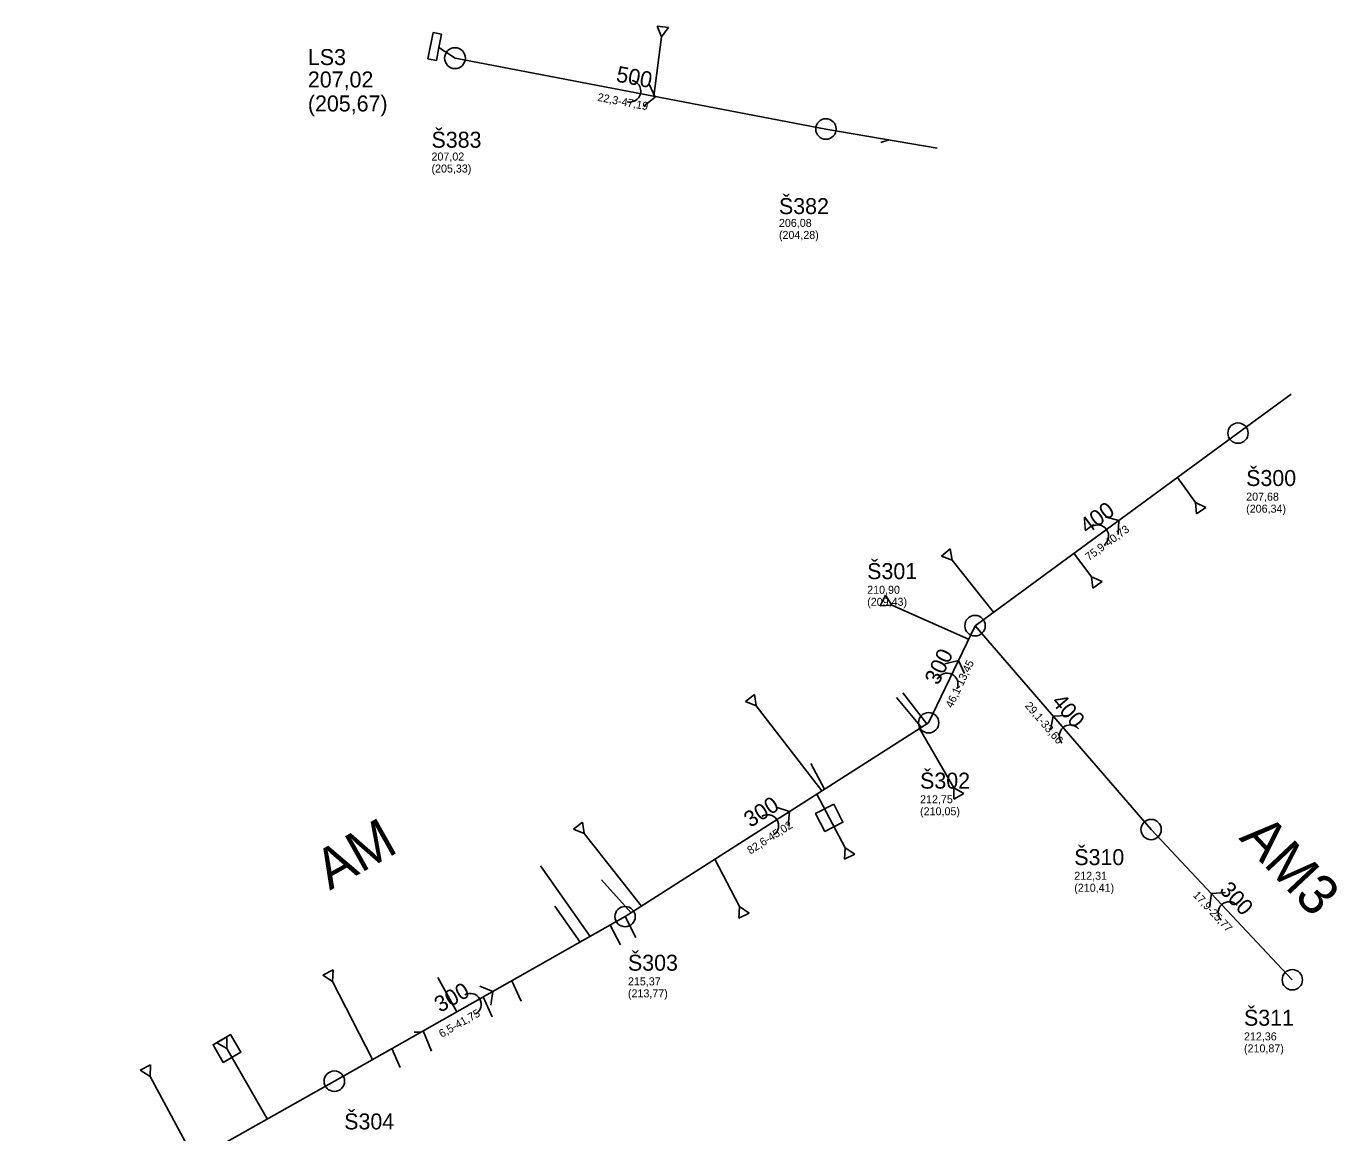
# Model space of a CAD drawing. Extents: x -574467 to -573663, y -1191209 to -1190406.
# Drawn here: x -574127.5 to -573963.7, y -1190544.6 to -1190406.2 of the extents above; entities that cross this region are included whole.
import ezdxf

# ---------------------------------------------------------------- set-up
doc = ezdxf.new("R2010")
doc.units = 0
for name, color, linetype in [('Vrstva 1', 7, 'Continuous'), ('Vrstva 12', 7, 'Continuous'), ('Vrstva 15', 7, 'Continuous'), ('Vrstva 29', 7, 'Continuous'), ('Vrstva 32', 7, 'Continuous'), ('Vrstva 35', 7, 'Continuous'), ('Vrstva 41', 7, 'Continuous'), ('Vrstva 44', 7, 'Continuous'), ('Vrstva 45', 7, 'Continuous'), ('Vrstva 56', 7, 'Continuous'), ('Vrstva 57', 7, 'Continuous')]:
    doc.layers.add(name, color=color, linetype=linetype)

# ---------------------------------------------------------------- blocks, each defined once
blk = doc.blocks.new('100')
at = {"layer": 'Vrstva 1'}
blk.add_circle((0, 0), 1.27, dxfattribs=at)
blk = doc.blocks.new('105')
at = {"layer": 'Vrstva 1'}
blk.add_lwpolyline([(-1.27, 1.27), (1.27, 1.27), (1.27, -1.27), (-1.27, -1.27), (-1.27, 1.27)], dxfattribs=at)
blk = doc.blocks.new('106')
at = {"layer": 'Vrstva 1'}
for p, q in [((1.25, 0.72), (0, 0)), ((0, 0), (1.25, -0.72)), ((1.25, -0.72), (1.25, 0.72))]:
    blk.add_line(p, q, dxfattribs=at)
blk = doc.blocks.new('91')
at = {"layer": 'Vrstva 1'}
blk.add_lwpolyline([(0.79, 1.37), (1.89, 0), (0.79, -1.38)], dxfattribs=at)
blk.add_arc((-1.37, 0), 1.37, 270, 90, dxfattribs=at)
blk = doc.blocks.new('86')
at = {"layer": 'Vrstva 1'}
blk.add_lwpolyline([(0.79, 1.37), (1.89, 0), (0.79, -1.38)], dxfattribs=at)
blk.add_arc((-1.37, 0), 1.37, 270, 90, dxfattribs=at)

msp = doc.modelspace()

# ---------------------------------------------------------------- linework, layer by layer
at = {"layer": 'Vrstva 12'}
for p, q in [((-574049.081, -1190414.968), (-574048.116, -1190407.558)), ((-574019.678, -1190420.432), (-574020.72, -1190420.75)), ((-573983.634, -1190462.641), (-573981.399, -1190465.764)), ((-573996.572, -1190472.118), (-573994.361, -1190475.053)), ((-574006.623, -1190479.48), (-574011.797, -1190472.997)), ((-574009.741, -1190482.866), (-574019.312, -1190478.584)), ((-574015.642, -1190493.883), (-574018.759, -1190490.132)), ((-574014.943, -1190493.436), (-574017.975, -1190489.569)), ((-574028.068, -1190501.822), (-574036.278, -1190491.183)), ((-574015.878, -1190494.034), (-574011.579, -1190501.422)), ((-574027.743, -1190501.614), (-574029.443, -1190498.394)), ((-574028.708, -1190502.231), (-574025.162, -1190508.924)), ((-574050.622, -1190516.232), (-574057.766, -1190507.142)), ((-574041.445, -1190510.369), (-574038.368, -1190516.29)), ((-574057.029, -1190520.008), (-574063.23, -1190511.189)), ((-574051.912, -1190517.055), (-574055.62, -1190512.939)), ((-574058.299, -1190520.727), (-574061.44, -1190516.216)), ((-574052.67, -1190517.54), (-574051.33, -1190520.158)), ((-574054.531, -1190518.594), (-574053.231, -1190521.056)), ((-574073.693, -1190529.443), (-574076.056, -1190525.134)), ((-574084.24, -1190535.415), (-574089.236, -1190525.631)), ((-574066.81, -1190525.546), (-574065.635, -1190528.097)), ((-574070.386, -1190527.571), (-574069.282, -1190530.063)), ((-574078.175, -1190531.981), (-574079.026, -1190532)), ((-574077.905, -1190531.828), (-574076.861, -1190534.337)), ((-574097.399, -1190542.834), (-574102.427, -1190534.028)), ((-574081.812, -1190534.04), (-574080.764, -1190536.416)), ((-574106.44, -1190547.919), (-574112.039, -1190537.511))]:
    msp.add_line(p, q, dxfattribs=at)
at = {"layer": 'Vrstva 15'}
for p, q in [((-574075.926, -1190408.899), (-574073.92, -1190410.22)), ((-574073.92, -1190410.22), (-574027.57, -1190419.08)), ((-574027.57, -1190419.08), (-574013.662, -1190421.462)), ((-573976.07, -1190457.1), (-573969.413, -1190452.221)), ((-574008.93, -1190481.17), (-573976.07, -1190457.1)), ((-574014.73, -1190493.3), (-574008.93, -1190481.17)), ((-573986.93, -1190506.65), (-574008.93, -1190481.17)), ((-574052.67, -1190517.54), (-574014.73, -1190493.3)), ((-573969.28, -1190525.43), (-573986.93, -1190506.65)), ((-574089, -1190538.11), (-574052.67, -1190517.54)), ((-574127.51, -1190559.77), (-574089, -1190538.11))]:
    msp.add_line(p, q, dxfattribs=at)
at = {"layer": 'Vrstva 32'}
msp.add_lwpolyline([(-574076.65, -1190407), (-574077.3, -1190410.31), (-574076.25, -1190410.51), (-574075.926, -1190408.899), (-574075.59, -1190407.23), (-574076.65, -1190407)], dxfattribs=at)

# ---------------------------------------------------------------- block references
at = {"layer": 'Vrstva 12'}
for name, p, xscale, yscale, rotation in [('106', (-574048.116, -1190407.558), 1.000191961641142, 1.000191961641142, 82.91099886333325), ('106', (-573981.399, -1190465.764), 0.9999999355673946, 0.9999999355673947, -55.0000006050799), ('106', (-574011.797, -1190472.997), 0.9999999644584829, 0.999999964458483, 129.00000106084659), ('106', (-573994.361, -1190475.053), 0.9999999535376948, 0.9999999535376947, -53.99999865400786), ('106', (-574019.312, -1190478.584), 1.0198568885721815, 1.0198568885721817, 153.60601759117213), ('106', (-574036.278, -1190491.183), 0.9999999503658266, 0.9999999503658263, 127.99999981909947), ('106', (-574011.579, -1190501.422), 0.999999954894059, 0.9999999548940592, -60.999999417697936), ('105', (-574027.142, -1190505.187), 0.999999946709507, 0.999999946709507, -62.999999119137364), ('106', (-574057.766, -1190507.142), 0.9999999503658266, 0.9999999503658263, 127.99999981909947), ('106', (-574025.162, -1190508.924), 0.999999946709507, 0.999999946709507, -62.999999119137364), ('106', (-574038.368, -1190516.29), 0.9999999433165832, 0.999999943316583, -64.0000000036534), ('106', (-574089.236, -1190525.631), 0.999999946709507, 0.999999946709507, 117.00000088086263), ('105', (-574102.427, -1190534.028), 0.9999999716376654, 0.9999999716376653, 119.99999896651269), ('106', (-574102.427, -1190534.028), 0.9999999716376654, 0.9999999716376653, 119.99999896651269), ('106', (-574112.039, -1190537.511), 0.9999999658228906, 0.9999999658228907, 117.99999982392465)]:
    msp.add_blockref(name, p, dxfattribs=dict(at, xscale=xscale, yscale=yscale, rotation=rotation))
at = {"layer": 'Vrstva 29'}
for p, xscale, yscale, rotation in [((-574073.92, -1190410.22), 1.025136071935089, 1.0251360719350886, 154.74924162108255), ((-574027.57, -1190419.08), 1.0073309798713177, 1.007330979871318, 167.86109216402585), ((-573976.07, -1190457.1), 0.9999999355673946, 0.9999999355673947, -145.00000060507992), ((-574008.93, -1190481.17), 1.0098116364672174, 1.0098116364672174, -169.38969904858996), ((-574014.73, -1190493.3), 0.9999999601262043, 0.9999999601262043, -131.99999877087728), ((-573986.93, -1190506.65), 0.9999999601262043, 0.9999999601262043, 131.99999877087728), ((-574052.67, -1190517.54), 0.9999999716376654, 0.9999999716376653, -150.00000103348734), ((-573969.28, -1190525.43), 0.9999999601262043, 0.9999999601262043, -48.0000012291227), ((-574089, -1190538.11), 1.0072562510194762, 1.0072562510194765, -151.23333635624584)]:
    msp.add_blockref('100', p, dxfattribs=dict(at, xscale=xscale, yscale=yscale, rotation=rotation))
at = {"layer": 'Vrstva 41'}
for name, p, xscale, yscale, rotation in [('86', (-574050.745, -1190414.65), 1.0045862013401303, 1.00458620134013, -13.17409066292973), ('91', (-573992.5, -1190469.135), 0.9999999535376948, 0.9999999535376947, 36.000001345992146), ('91', (-574011.83, -1190487.235), 0.9999999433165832, 0.999999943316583, 64.0000000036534), ('86', (-573997.93, -1190493.91), 0.9999999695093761, 0.9999999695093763, 131.00000134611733), ('91', (-574033.7, -1190505.42), 0.9999999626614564, 0.9999999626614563, 32.99999840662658), ('86', (-573978.105, -1190516.04), 0.9999999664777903, 0.9999999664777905, 132.99999806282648), ('91', (-574070.835, -1190527.825), 0.9999999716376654, 0.9999999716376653, 29.999998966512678)]:
    msp.add_blockref(name, p, dxfattribs=dict(at, xscale=xscale, yscale=yscale, rotation=rotation))

# ---------------------------------------------------------------- texts
at = {"layer": 'Vrstva 32'}
for s, p in [('LS3', (-574092.309, -1190411.087)), ('207,02 ', (-574092.309, -1190413.887)), ('(205,67)', (-574092.309, -1190416.887))]:
    msp.add_text(s, height=2, dxfattribs=at).set_placement(p)
at = {"layer": 'Vrstva 35'}
for s, rotation, p in [('AM', 29.36, (-574089.579, -1190514.302)), ('AM3', 313.22, (-573976.038, -1190507.78))]:
    msp.add_text(s, height=5, rotation=rotation, dxfattribs=at).set_placement(p)
at = {"layer": 'Vrstva 44'}
for s, rotation, p in [('500', 349.18, (-574053.885, -1190413.135)), ('400', 36.22, (-573994.912, -1190469.786)), ('300', 64.45, (-574013.529, -1190488.7)), ('400', 310.81, (-573999.47, -1190490.744)), ('300', 32.57, (-574037.006, -1190506.465)), ('300', 313.22, (-573978.507, -1190514.304)), ('300', 29.52, (-574075.79, -1190529.589))]:
    msp.add_text(s, height=2, rotation=rotation, dxfattribs=at).set_placement(p)
at = {"layer": 'Vrstva 45'}
for s, rotation, p in [('22,3-47,19', 349.18, (-574056.174, -1190415.548)), ('75,9-40,73', 36.22, (-573994.709, -1190473.101)), ('46,1-13,45', 64.45, (-574011.782, -1190491.534)), ('29,1-33,66', 310.81, (-574002.768, -1190491.217)), ('82,6-45,02', 32.57, (-574037.012, -1190509.792)), ('17,9-25,77', 313.22, (-573981.776, -1190514.908)), ('6,5-41,75', 29.52, (-574075.586, -1190532.696))]:
    msp.add_text(s, height=1, rotation=rotation, dxfattribs=at).set_placement(p)
at = {"layer": 'Vrstva 56'}
for s, p in [('207,02 ', (-574076.86, -1190423.02)), ('(205,33)', (-574076.86, -1190424.52)), ('206,08 ', (-574033.44, -1190431.32)), ('(204,28)', (-574033.44, -1190432.82)), ('207,68 ', (-573975.05, -1190465.54)), ('(206,34)', (-573975.05, -1190467.04)), ('210,90 ', (-574022.41, -1190477.18)), ('(209,43)', (-574022.41, -1190478.68)), ('212,75 ', (-574015.8, -1190503.37)), ('(210,05)', (-574015.8, -1190504.87)), ('212,31 ', (-573996.53, -1190512.93)), ('(210,41)', (-573996.53, -1190514.43)), ('215,37 ', (-574052.31, -1190526.13)), ('(213,77)', (-574052.31, -1190527.63)), ('212,36 ', (-573975.32, -1190533.01)), ('(210,87)', (-573975.32, -1190534.51))]:
    msp.add_text(s, height=1, dxfattribs=at).set_placement(p)
at = {"layer": 'Vrstva 57'}
for s, p in [('Š383', (-574076.86, -1190421.42)), ('Š382', (-574033.44, -1190429.72)), ('Š300', (-573975.05, -1190463.71)), ('Š301', (-574022.41, -1190475.35)), ('Š302', (-574015.8, -1190501.54)), ('Š310', (-573996.53, -1190511.1)), ('Š303', (-574052.31, -1190524.3)), ('Š311', (-573975.32, -1190531.18)), ('Š304', (-574087.77, -1190544.14))]:
    msp.add_text(s, height=2, dxfattribs=at).set_placement(p)

doc.saveas('drawing.dxf')
